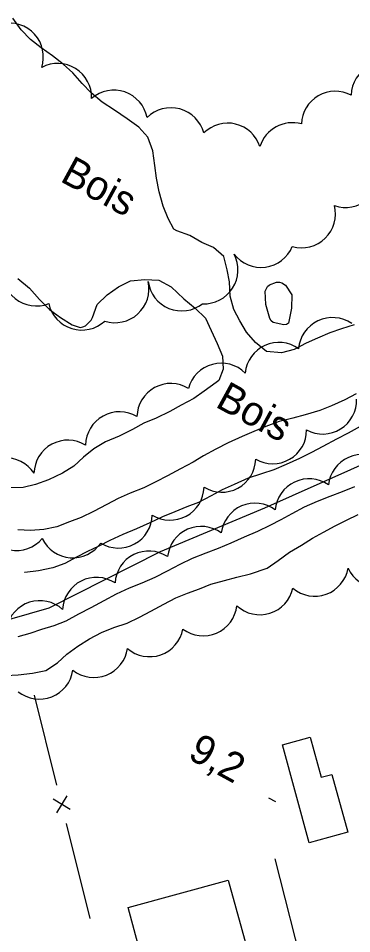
# Model space of a CAD drawing. Extents: x 219136 to 222520, y 5421589 to 5424530.
# Drawn here: x 221462.3 to 221496.4, y 5423239.8 to 5423333.2 of the extents above; entities that cross this region are included whole.
import ezdxf

# ---------------------------------------------------------------- set-up
doc = ezdxf.new("R2010")
doc.units = 0
for name, color, linetype in [('Level 1', 7, 'Continuous'), ('Level 19', 7, 'Continuous'), ('Level 2', 7, 'Continuous'), ('Level 3', 7, 'Continuous'), ('Level 31', 7, 'Continuous'), ('Level 37', 7, 'Continuous'), ('Level 4', 7, 'Continuous'), ('Level 44', 7, 'Continuous')]:
    doc.layers.add(name, color=color, linetype=linetype)

msp = doc.modelspace()

# ---------------------------------------------------------------- linework, layer by layer
at = {"layer": 'Level 1'}
for points in [[(221478.19, 5423311.69), (221477.6, 5423312.79), (221477.11, 5423314.06), (221476.71, 5423315.53), (221476.41, 5423316.92), (221476.24, 5423318.19), (221476.05, 5423319.7), (221475.53, 5423321.08), (221474.62, 5423322.12), (221473.43, 5423322.96), (221472.14, 5423323.84), (221470.86, 5423324.65), (221469.74, 5423325.61), (221468.84, 5423326.57), (221467.86, 5423327.67), (221466.88, 5423328.54), (221465.78, 5423329.38), (221464.62, 5423330.2), (221463.54, 5423331.07), (221462.6, 5423332.04), (221461.75, 5423333.22)], [(221496.61, 5423301.93), (221495.34, 5423301.55), (221494.15, 5423301.12), (221492.87, 5423300.59), (221491.72, 5423300.06), (221490.48, 5423299.44), (221489.18, 5423299.08), (221487.67, 5423299.22), (221486.55, 5423300.13), (221485.63, 5423301.2), (221484.94, 5423302.34), (221484.32, 5423303.5), (221483.95, 5423304.87), (221483.87, 5423306.33), (221483.65, 5423307.56), (221483.31, 5423308.93), (221482.26, 5423309.85), (221481.05, 5423310.34), (221479.83, 5423311.05), (221478.51, 5423311.55), (221478.19, 5423311.69)], [(221462.24, 5423306.68), (221463.43, 5423305.7), (221464.47, 5423304.54), (221465.5, 5423303.5), (221466.6, 5423302.68), (221467.81, 5423301.93), (221468.62, 5423301.69), (221468.91, 5423301.75), (221469.15, 5423301.86), (221469.76, 5423302.42), (221469.87, 5423302.7), (221470.36, 5423304.03), (221471.39, 5423305.02), (221472.53, 5423305.81), (221473.77, 5423306.42), (221475.23, 5423306.58), (221476.67, 5423306.49), (221477.92, 5423305.81), (221479.23, 5423304.59), (221480.36, 5423303.63), (221481.42, 5423302.62), (221482.02, 5423301.38), (221482.61, 5423300.03), (221483.15, 5423298.74)], [(221483.15, 5423298.74), (221483.22, 5423297.41), (221482.79, 5423296.28), (221482.53, 5423296.06), (221481.3, 5423295.17), (221480.24, 5423294.44), (221478.95, 5423293.74), (221477.78, 5423293.12), (221476.38, 5423292.44), (221475.13, 5423291.9), (221473.98, 5423291.28), (221472.6, 5423290.6), (221471.2, 5423290.02), (221470.01, 5423289.3), (221468.97, 5423288.45), (221467.97, 5423287.53), (221466.82, 5423286.8), (221465.39, 5423286.14), (221464.07, 5423285.64), (221462.81, 5423285.34), (221461.5, 5423285.33)]]:
    msp.add_lwpolyline(points, dxfattribs=at)
at = {"layer": 'Level 19'}
msp.add_lwpolyline([(221488.5, 5423247.46), (221491.61, 5423235.28), (221493.17, 5423228.24), (221493.94, 5423226.2), (221495.2, 5423224.46)], dxfattribs=at)
at = {"layer": 'Level 2'}
for points in [[(221490.24, 5423305.01), (221490.22, 5423303.65), (221489.92, 5423302.11), (221489.69, 5423301.97), (221489.44, 5423301.95), (221488.33, 5423302.19), (221488.15, 5423302.37), (221487.99, 5423302.6), (221487.59, 5423304.02), (221487.53, 5423305.38), (221487.76, 5423305.87), (221487.97, 5423306.03), (221488.7, 5423306.3), (221488.99, 5423306.29), (221489.23, 5423306.24), (221489.59, 5423305.99), (221490.24, 5423305.01)], [(221496.81, 5423294.9), (221495.65, 5423294.31), (221494.32, 5423293.69), (221493.1, 5423293.21), (221491.6, 5423292.75), (221490.35, 5423292.44), (221488.94, 5423292.07), (221487.61, 5423291.56), (221486.36, 5423291.05), (221485.19, 5423290.55), (221483.74, 5423289.89), (221482.49, 5423289.25), (221481.23, 5423288.57), (221480.16, 5423287.93), (221478.89, 5423287.24), (221477.55, 5423286.53), (221476.36, 5423285.94), (221475.13, 5423285.33), (221473.74, 5423284.76), (221472.51, 5423284.24), (221471.34, 5423283.63), (221469.98, 5423282.9), (221468.71, 5423282.3), (221467.53, 5423281.84), (221466.24, 5423281.33), (221464.9, 5423281.05), (221463.56, 5423280.95), (221462.24, 5423281.03)], [(221497.22, 5423291.56), (221495.99, 5423290.9), (221494.81, 5423290.27), (221493.42, 5423289.53), (221492.25, 5423288.91), (221491.02, 5423288.31), (221489.66, 5423287.69), (221488.4, 5423287.16), (221487.16, 5423286.73), (221485.78, 5423286.31), (221484.35, 5423285.66), (221483.14, 5423285.1), (221482.01, 5423284.51), (221480.72, 5423283.83), (221479.51, 5423283.37), (221478.31, 5423282.88), (221477.05, 5423282.35), (221475.75, 5423281.75), (221474.37, 5423281.14), (221472.97, 5423280.57), (221471.65, 5423279.95), (221470.52, 5423279.37), (221469.38, 5423278.83), (221468.25, 5423278.23), (221467.04, 5423277.6), (221465.83, 5423277.15), (221464.37, 5423276.84), (221462.97, 5423276.67), (221462.92, 5423276.66)], [(221477.54, 5423276.83), (221478.85, 5423277.53), (221480.11, 5423278.14), (221481.51, 5423278.67), (221482.77, 5423279.15), (221484.06, 5423279.71), (221485.4, 5423280.3), (221486.79, 5423280.88), (221488.04, 5423281.5), (221489.15, 5423282.1), (221490.29, 5423282.7), (221491.56, 5423283.37), (221492.86, 5423283.96), (221494.16, 5423284.48), (221495.43, 5423284.95), (221496.69, 5423285.45)], [(221490.01, 5423278.74), (221491.25, 5423279.48), (221492.37, 5423280.19), (221493.5, 5423280.79), (221494.68, 5423281.43), (221495.84, 5423282.03), (221497.02, 5423282.59)], [(221461.02, 5423266.16), (221462.3, 5423266.25), (221463.76, 5423266.39), (221465.11, 5423266.69), (221466.29, 5423267.47), (221467.25, 5423268.33), (221468.4, 5423269.17), (221469.58, 5423269.9), (221470.81, 5423270.55), (221472.05, 5423271.05), (221473.41, 5423271.52), (221474.67, 5423272.11), (221475.85, 5423272.74), (221477.16, 5423273.44), (221478.4, 5423274.09), (221479.59, 5423274.57), (221480.81, 5423275.02), (221481.98, 5423275.47), (221483.36, 5423275.87), (221484.63, 5423276.2), (221486.04, 5423276.54), (221487.72, 5423277.11), (221488.85, 5423277.9), (221490.01, 5423278.74)], [(221462.28, 5423270.16), (221463.5, 5423270.49), (221464.7, 5423270.89), (221465.96, 5423271.26), (221467.2, 5423271.76), (221468.5, 5423272.45), (221469.76, 5423273.12), (221471.08, 5423273.83), (221472.33, 5423274.5), (221473.66, 5423275.11), (221474.97, 5423275.61), (221476.29, 5423276.19), (221477.54, 5423276.83)]]:
    msp.add_lwpolyline(points, dxfattribs=at)
at = {"layer": 'Level 3'}
msp.add_line((221487.88, 5423253.69), (221488.59, 5423253.31), dxfattribs=at)
at = {"layer": 'Level 31'}
for points in [[(221492.03, 5423249.11), (221489.29, 5423259.08), (221492.13, 5423259.86), (221493.25, 5423255.78), (221494.34, 5423256.08), (221495.96, 5423250.19)], [(221473.51, 5423242.49), (221483.76, 5423245.3), (221485.91, 5423237.43), (221485.18, 5423237.22), (221485.36, 5423236.55), (221482.16, 5423235.67), (221481.93, 5423236.5), (221475.62, 5423234.78)]]:
    msp.add_lwpolyline(points, close=True, dxfattribs=at)
at = {"layer": 'Level 37'}
for p, q in [((221467.59, 5423252.51), (221465.87, 5423253.54)), ((221467.25, 5423253.88), (221466.22, 5423252.17))]:
    msp.add_line(p, q, dxfattribs=at)
for points in [[(221466.25, 5423254.97), (221463.96, 5423264.16)], [(221469.63, 5423241.38), (221467.21, 5423251.08)]]:
    msp.add_lwpolyline(points, dxfattribs=at)
at = {"layer": 'Level 4'}
msp.add_lwpolyline([(221456.8, 5423271.43), (221459.63, 5423271.4), (221465.44, 5423273.08), (221476.83, 5423278.81), (221487.5, 5423283.27), (221502.25, 5423289.83), (221514.48, 5423294.21), (221522.96, 5423297.92), (221532.43, 5423302.84), (221541.1, 5423307.76), (221549.67, 5423312.48), (221554.39, 5423314.28)], dxfattribs=at)
at = {"layer": 'Level 44'}
for centre, start, end in [((221461.395, 5423329.272), 342.05436, 102.05436), ((221466.326, 5423325.15), 358.16198, 118.16198), ((221499.773, 5423325.27), 58.14758, 178.14758), ((221472.062, 5423322.426), 11.02293, 131.02293), ((221494.692, 5423322.319), 62.13896, 178.03313), ((221477.905, 5423320.632), 14.84666, 134.84666), ((221483.694, 5423319.061), 17.96677, 134.78588), ((221490.297, 5423319.102), 74.3845, 162.74304), ((221495.777, 5423317.38), 250.19362, 10.19362), ((221491.245, 5423313.271), 254.19357, 14.19357), ((221487.1, 5423311.263), 217.51915, 337.51915), ((221481.279, 5423307.554), 267.47994, 27.47994), ((221464.142, 5423307.333), 171.37685, 291.37685), ((221472.187, 5423305.623), 252.29437, 12.29437), ((221479.004, 5423306.831), 187.80225, 307.80225), ((221468.785, 5423304.869), 192.6959, 312.6959), ((221494.4, 5423299.222), 55.35078, 175.35078), ((221488.928, 5423296.688), 54.3413, 174.3413), ((221483.041, 5423294.571), 45.22131, 165.22131), ((221477.885, 5423292.499), 58.56261, 178.56261), ((221493.408, 5423294.267), 241.67837, 1.67837), ((221472.64, 5423289.615), 59.04935, 179.04935), ((221488.3, 5423291.23), 239.78872, 359.78872), ((221467.367, 5423286.718), 58.51966, 178.51966), ((221461.007, 5423284.909), 33.22338, 153.22338), ((221483.094, 5423288.329), 238.47851, 358.47851), ((221497.43, 5423285.243), 53.62714, 173.62714), ((221492.016, 5423282.779), 55.31818, 175.31818), ((221477.821, 5423285.485), 238.19536, 358.19536), ((221486.483, 5423280.292), 53.09571, 173.09571), ((221472.532, 5423282.635), 238.43979, 358.43979), ((221462.102, 5423282.389), 199.50906, 319.50906), ((221480.994, 5423277.916), 53.71086, 173.71086), ((221467.86, 5423281.638), 205.63844, 325.63844), ((221475.641, 5423275.406), 56.53104, 176.53104), ((221492.59, 5423277.721), 229.85083, 349.85083), ((221499.135, 5423278.584), 205.16579, 325.16579), ((221470.286, 5423272.717), 56.79716, 176.79716), ((221486.976, 5423275.827), 227.42948, 347.42948), ((221464.504, 5423270.341), 47.88782, 167.88782), ((221481.191, 5423273.677), 233.35629, 353.35629), ((221475.721, 5423271.548), 229.16682, 349.16682), ((221470.028, 5423269.424), 231.76139, 351.76139), ((221464.459, 5423267.22), 231.4082, 351.4082)]:
    msp.add_arc(centre, 3.464, start, end, dxfattribs=at)

# ---------------------------------------------------------------- texts
at = {"layer": 'Level 3'}
msp.add_text('9,2', height=3, rotation=331.383, dxfattribs=at).set_placement((221479.5, 5423257.76))
at = {"layer": 'Level 44'}
for p in [(221466.46, 5423316.65), (221482.32, 5423293.64)]:
    msp.add_text('Bois', height=3, rotation=331.35475, dxfattribs=at).set_placement(p)

doc.saveas('drawing.dxf')
